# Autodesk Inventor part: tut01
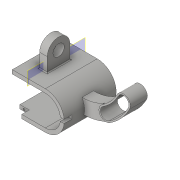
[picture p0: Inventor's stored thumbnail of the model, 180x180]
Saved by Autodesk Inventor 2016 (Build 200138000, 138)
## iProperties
Created: 2015-03
Part Number: tut01
Material: Generic
Document SubType Name: Modeling
Designer: Sandeep
Density: 1 g/cm^3
Appearance: Default
Author: Sandeep
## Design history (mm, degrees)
sketch "Sketch1"
  geometry: L1 (35, 20)-(0, 20); L2 (0, -20)-(35, -20); L3 (35, 16)-(0, 16); L4 (0, -16)-(35, -16); L5 (35, 16)-(35, 20); L6 (35, -16)-(35, -20); L7 (42.148, 0)-(-37.683, 0); A1 r 20 centre (0, 0) between (0, 20) and (0, -20); A2 r 16 centre (0, 0) between (0, 16) and (0, -16); 1 further point
  constraints: 14 end point, 4 point on circle, 2 centre point, 2 horizontal, 2 parallel, 2 tangent, 2 vertical, 1 coincident, 1 point on line, 3 other
  dimensions: "d0" = 35 distance of L2.start L2.end; "d1" = 20 radius of A1; "d2" = 4 distance between parallel lines of L2 L4
extrude "Extrusion1" new body sketch "Sketch1" stored distance "d3" = 55; taper "d4" = 0 deg
sketch "Sketch4"
  geometry: L1 (0, 54.055)-(0, -53.115); A1 r 45 centre (-17.5, 55) between (-57.434, 34.257) and (-17.32, 10); A2 r 7.5 centre (-64.09, 30.799) between (-57.434, 34.257) and (-70.745, 27.342); A3 r 60 centre (-17.5, 55) between (-70.745, 27.342) and (-19.372, -4.971); A4 r 20 centre (0, 0) between (-17.32, 10) and (-19.372, -4.971); A5 r 20 centre (0, 0) between (0, 20) and (0, -20) reference; A6 r 20 centre (0, 0) between (0, 20) and (0, -20) reference; A7 r 52.5 centre (-17.5, 55) between (-64.09, 30.799) and (-19.837, 2.552); 1 further point
  constraints: 13 point on circle, 5 centre point, 2 coincident, 2 end point, 2 tangent, 1 concentric, 1 point on line, 1 vertical
  dimensions: "d7" = 45 radius of A1; "d8" = 60 radius of A3; "d9" = 17.5 distance from line of L1 A1.centre; "d10" = 55 vertical distance of point (0, 0) A1.centre; "d13" = 60 deg dimension on A1.centre A2.centre A7.end
extrude "Extrusion2" join sketch "Sketch4" stored distance "d11" = 12; taper "d12" = 0 deg
sketch "Sketch6"
  geometry: A1 r 52.5 centre (-17.5, 55) between (-64.09, 30.799) and (-45.747, 10.747); A2 r 60 centre (-17.5, 55) between (-70.745, 27.342) and (-49.783, 4.425); A3 r 45 centre (-17.5, 55) between (-57.434, 34.257) and (-41.712, 17.069); A4 r 7.5 centre (-64.09, 30.799) between (-57.434, 34.257) and (-70.745, 27.342); A5 r 7.5 centre (-45.747, 10.747) between (-49.783, 4.425) and (-41.712, 17.069); A6 r 45 centre (-17.5, 55) between (-57.434, 34.257) and (-17.32, 10) reference; A7 r 60 centre (-17.5, 55) between (-70.745, 27.342) and (-19.372, -4.971) reference; A8 r 7.5 centre (-64.09, 30.799) between (-57.434, 34.257) and (-70.745, 27.342) reference; 2 further points
  constraints: 12 point on circle, 5 centre point, 4 tangent, 3 concentric
  dimensions: "d14" = 30 deg dimension on A1.centre A1.end A1.start
extrude "Extrusion3" join sketch "Sketch6" stored distance "d15" = 18; taper "d16" = 0 deg
sketch "Sketch7"
  geometry: A1 r 52.5 centre (17.5, 55) between (45.747, 10.747) and (64.09, 30.799); A2 r 58.5 centre (17.5, 55) between (48.976, 5.689) and (69.414, 28.034); A3 r 46.5 centre (17.5, 55) between (42.519, 15.804) and (58.765, 33.565); A4 r 6 centre (45.747, 10.747) between (42.519, 15.804) and (48.976, 5.689); A5 r 6 centre (64.09, 30.799) between (69.414, 28.034) and (58.765, 33.565); A6 r 45 centre (17.5, 55) between (41.712, 17.069) and (57.434, 34.257) reference; A7 r 60 centre (17.5, 55) between (49.783, 4.425) and (70.745, 27.342) reference; A8 r 7.5 centre (64.09, 30.799) between (70.745, 27.342) and (57.434, 34.257) reference; A9 r 7.5 centre (45.747, 10.747) between (41.712, 17.069) and (49.783, 4.425) reference; 1 further point
  constraints: 10 point on circle, 5 centre point, 4 concentric, 4 tangent
  dimensions: "d17" = 6 radius of A5
extrude "Extrusion4" cut sketch "Sketch7" stored distance "d18" = 18; taper "d19" = 0 deg
workplane "Work Plane1"
sketch "Sketch8"
  geometry: 1 further point
sketch "Sketch9"
  geometry: L1 (0, 55)-(0, 0) reference; L2 (0, 39.5)-(15, 39.5); L3 (15, 15.5)-(0, 15.5); L4 (0, 39.5)-(0, 15.5); L5 (-20, 27.5)-(24.854, 27.5); A1 r 12 centre (15, 27.5) between (15, 15.5) and (15, 39.5)
  constraints: 8 end point, 3 point on line, 2 horizontal, 2 point on circle, 2 tangent, 1 centre point, 1 collinear, 1 parallel
  dimensions: "d21" = 12 radius of A1; "d22" = 15 distance from line of L1 A1.centre
extrude "Extrusion5" join sketch "Sketch9" stored distance "d23" = 8; taper "d24" = 0 deg
sketch "Sketch10"
  geometry: C1 r 6 at (15, 27.5); A1 r 12 centre (15, 27.5) between (15, 15.5) and (15, 39.5) reference; 1 further point
  constraints: 1 centre point, 1 concentric
  dimensions: "d25" = 12 diameter of C1
extrude "Extrusion6" cut sketch "Sketch10" distance "d26" = 8; taper "d27" = 0 deg
fillet "Fillet1" dims "d28" = 1
sketch "Sketch11"
  geometry: L1 (15.875, -2)-(19.9, -2); L2 (15.875, 2)-(19.9, 2); L3 (0, 0)-(6.778, 0); L4 (-35, -20)-(-35, -16) reference; L5 (-35, -20)-(-25, -20); L6 (-25, -20)-(-25, -16); L7 (-25, -16)-(-35, -16); L8 (-35, -16)-(-35, -20); A1 r 16 centre (0, 0) between (0, -16) and (0, 16) reference; A2 r 20 centre (0, 0) between (0, -20) and (0, 20) reference; A3 r 20 centre (0, 0) between (19.9, -2) and (19.9, 2); A4 r 16 centre (0, 0) between (15.875, -2) and (15.875, 2); 1 further point
  constraints: 14 end point, 8 point on circle, 3 horizontal, 3 parallel, 2 centre point, 2 coincident, 1 perpendicular, 1 point on line, 1 other
  dimensions: "d30" = 2 distance from line of L3.end L2; "d31" = 10 distance between parallel lines of L4 L6
extrude "Extrusion7" cut sketch "Sketch11" distance "d32" = 8; taper "d33" = 0 deg
hole "Hole1" diameter "d36" = 2; stored, may be unused: countersink angle "d40" = 90 deg, drill point angle "d42" = 118 deg; dims "d34" = 10, "d35" = 10, "d37" = 6, "d38" = 4, "d39" = 2, "d41" = 4
body "Solid1"
other parameters: "d20" = -17.5
